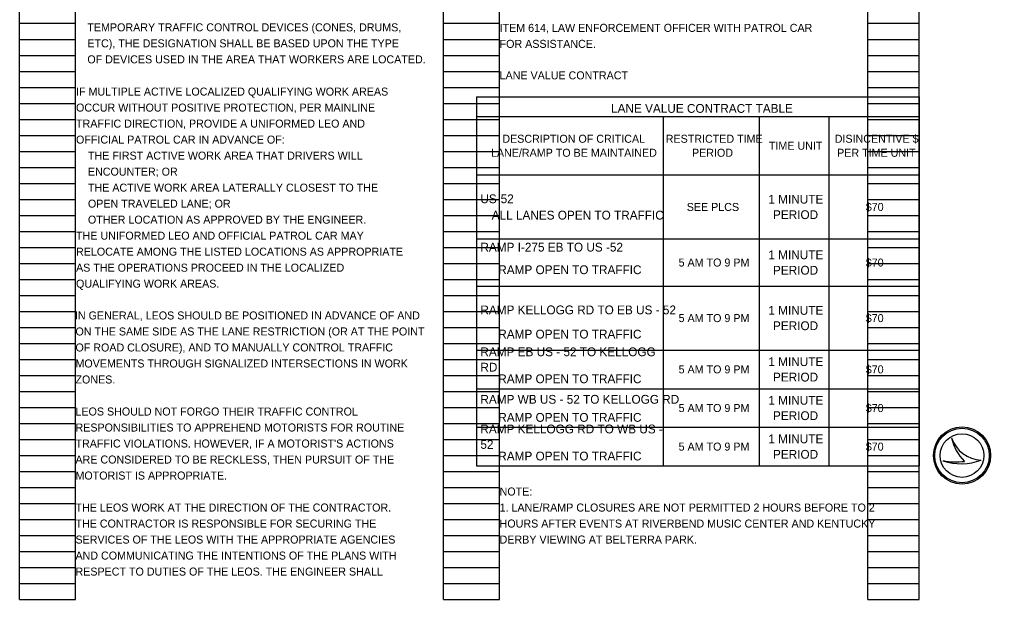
# Model space of a CAD drawing. Extents: x -21.1 to 72.2, y 0 to 46.6.
# Drawn here: x 55.22 to 72.21, y 26.26 to 36.41 of the extents above; entities that cross this region are included whole.
import ezdxf

# ---------------------------------------------------------------- set-up
doc = ezdxf.new("R2010")
doc.units = 0
for name, color, linetype in [('Default', 7, 'Continuous'), ('SH_Data', 7, 'Continuous'), ('SH_Text', 7, 'Continuous')]:
    doc.layers.add(name, color=color, linetype=linetype)

msp = doc.modelspace()

# ---------------------------------------------------------------- linework, layer by layer
at = {"layer": 'Default'}
for p, q in [((63.22, 35.056), (70.962, 35.056)), ((63.22, 35.056), (63.22, 28.6)), ((70.962, 35.056), (70.962, 28.6)), ((63.22, 34.71), (66.482, 34.71)), ((66.482, 34.71), (70.962, 34.71)), ((66.482, 34.71), (66.482, 28.6)), ((68.162, 34.71), (68.162, 28.6)), ((69.38, 34.71), (69.38, 28.6)), ((63.22, 33.689), (70.962, 33.689)), ((63.22, 32.569), (70.962, 32.569)), ((63.22, 31.745), (70.962, 31.745)), ((63.22, 30.625), (70.962, 30.625)), ((63.22, 29.95), (70.962, 29.95)), ((63.22, 29.275), (70.962, 29.275)), ((63.22, 28.6), (70.962, 28.6))]:
    msp.add_line(p, q, dxfattribs=at)
at = {"layer": 'SH_Data'}
for p, q in [((55.222, 26.261), (55.222, 46.421)), ((56.202, 26.261), (56.202, 46.421)), ((62.642, 26.261), (62.642, 46.421)), ((63.622, 26.261), (63.622, 46.421)), ((70.062, 26.261), (70.062, 46.421)), ((70.962, 26.261), (70.962, 46.421)), ((55.222, 36.341), (56.202, 36.341)), ((62.642, 36.341), (63.622, 36.341)), ((70.062, 36.341), (70.962, 36.341)), ((55.222, 36.061), (56.202, 36.061)), ((62.642, 36.061), (63.622, 36.061)), ((70.062, 36.061), (70.962, 36.061)), ((55.222, 35.781), (56.202, 35.781)), ((62.642, 35.781), (63.622, 35.781)), ((70.062, 35.781), (70.962, 35.781)), ((55.222, 35.501), (56.202, 35.501)), ((62.642, 35.501), (63.622, 35.501)), ((70.062, 35.501), (70.962, 35.501)), ((55.222, 35.221), (56.202, 35.221)), ((62.642, 35.221), (63.622, 35.221)), ((70.062, 35.221), (70.962, 35.221)), ((55.222, 34.941), (56.202, 34.941)), ((62.642, 34.941), (63.622, 34.941)), ((70.062, 34.941), (70.962, 34.941)), ((55.222, 34.661), (56.202, 34.661)), ((62.642, 34.661), (63.622, 34.661)), ((70.062, 34.661), (70.962, 34.661)), ((55.222, 34.381), (56.202, 34.381)), ((62.642, 34.381), (63.622, 34.381)), ((70.062, 34.381), (70.962, 34.381)), ((55.222, 34.101), (56.202, 34.101)), ((62.642, 34.101), (63.622, 34.101)), ((70.062, 34.101), (70.962, 34.101)), ((55.222, 33.821), (56.202, 33.821)), ((62.642, 33.821), (63.622, 33.821)), ((70.062, 33.821), (70.962, 33.821)), ((55.222, 33.541), (56.202, 33.541)), ((62.642, 33.541), (63.622, 33.541)), ((70.062, 33.541), (70.962, 33.541)), ((55.222, 33.261), (56.202, 33.261)), ((62.642, 33.261), (63.622, 33.261)), ((70.062, 33.261), (70.962, 33.261)), ((55.222, 32.981), (56.202, 32.981)), ((62.642, 32.981), (63.622, 32.981)), ((70.062, 32.981), (70.962, 32.981)), ((55.222, 32.701), (56.202, 32.701)), ((62.642, 32.701), (63.622, 32.701)), ((70.062, 32.701), (70.962, 32.701)), ((55.222, 32.421), (56.202, 32.421)), ((62.642, 32.421), (63.622, 32.421)), ((70.062, 32.421), (70.962, 32.421)), ((55.222, 32.141), (56.202, 32.141)), ((62.642, 32.141), (63.622, 32.141)), ((70.062, 32.141), (70.962, 32.141)), ((55.222, 31.861), (56.202, 31.861)), ((62.642, 31.861), (63.622, 31.861)), ((70.062, 31.861), (70.962, 31.861)), ((55.222, 31.581), (56.202, 31.581)), ((62.642, 31.581), (63.622, 31.581)), ((70.062, 31.581), (70.962, 31.581)), ((55.222, 31.301), (56.202, 31.301)), ((62.642, 31.301), (63.622, 31.301)), ((70.062, 31.301), (70.962, 31.301)), ((55.222, 31.021), (56.202, 31.021)), ((62.642, 31.021), (63.622, 31.021)), ((70.062, 31.021), (70.962, 31.021)), ((55.222, 30.741), (56.202, 30.741)), ((62.642, 30.741), (63.622, 30.741)), ((70.062, 30.741), (70.962, 30.741)), ((55.222, 30.461), (56.202, 30.461)), ((62.642, 30.461), (63.622, 30.461)), ((70.062, 30.461), (70.962, 30.461)), ((55.222, 30.181), (56.202, 30.181)), ((62.642, 30.181), (63.622, 30.181)), ((70.062, 30.181), (70.962, 30.181)), ((55.222, 29.901), (56.202, 29.901)), ((62.642, 29.901), (63.622, 29.901)), ((70.062, 29.901), (70.962, 29.901)), ((55.222, 29.621), (56.202, 29.621)), ((62.642, 29.621), (63.622, 29.621)), ((70.062, 29.621), (70.962, 29.621)), ((55.222, 29.341), (56.202, 29.341)), ((62.642, 29.341), (63.622, 29.341)), ((70.062, 29.341), (70.962, 29.341)), ((55.222, 29.061), (56.202, 29.061)), ((62.642, 29.061), (63.622, 29.061)), ((70.062, 29.061), (70.962, 29.061)), ((71.529, 29.091), (71.529, 29.091)), ((55.222, 28.781), (56.202, 28.781)), ((62.642, 28.781), (63.622, 28.781)), ((70.062, 28.781), (70.962, 28.781)), ((71.379, 28.691), (71.379, 28.691)), ((72.049, 28.7), (72.049, 28.7)), ((55.222, 28.501), (56.202, 28.501)), ((62.642, 28.501), (63.622, 28.501)), ((70.062, 28.501), (70.962, 28.501)), ((55.222, 28.221), (56.202, 28.221)), ((62.642, 28.221), (63.622, 28.221)), ((70.062, 28.221), (70.962, 28.221)), ((55.222, 27.941), (56.202, 27.941)), ((62.642, 27.941), (63.622, 27.941)), ((70.062, 27.941), (70.962, 27.941)), ((55.222, 27.661), (56.202, 27.661)), ((62.642, 27.661), (63.622, 27.661)), ((70.062, 27.661), (70.962, 27.661)), ((55.222, 27.381), (56.202, 27.381)), ((62.642, 27.381), (63.622, 27.381)), ((70.062, 27.381), (70.962, 27.381)), ((55.222, 27.101), (56.202, 27.101)), ((62.642, 27.101), (63.622, 27.101)), ((70.062, 27.101), (70.962, 27.101)), ((55.222, 26.821), (56.202, 26.821)), ((62.642, 26.821), (63.622, 26.821)), ((70.062, 26.821), (70.962, 26.821)), ((55.222, 26.541), (56.202, 26.541)), ((62.642, 26.541), (63.622, 26.541)), ((70.062, 26.541), (70.962, 26.541)), ((55.222, 26.261), (56.202, 26.261)), ((62.642, 26.261), (63.622, 26.261)), ((70.062, 26.261), (70.962, 26.261))]:
    msp.add_line(p, q, dxfattribs=at)
for radius in [0.5, 0.477, 0.477, 0.382]:
    msp.add_circle((71.712, 28.781), radius, dxfattribs=at)
for centre, radius, start, end in [((72.077, 29.279), 0.58, 198.9257, 198.9319), ((72.308, 29.251), 0.796, 191.6379, 191.6421), ((72.077, 29.279), 0.58, 198.9319, 267.1657), ((72.308, 29.251), 0.796, 191.6421, 226.0947), ((71.701, 29.651), 1.013, 251.4576, 290.0832), ((71.61, 29.936), 1.266, 259.4964, 259.4995), ((71.701, 29.651), 1.013, 251.4527, 251.4576), ((71.61, 29.936), 1.266, 259.4995, 276.6672)]:
    msp.add_arc(centre, radius, start, end, dxfattribs=at)

# ---------------------------------------------------------------- texts
at = {"layer": 'Default'}
for s, height, p in [('LANE VALUE CONTRACT', 0.14, (63.622, 35.361)), ('LANE VALUE CONTRACT TABLE', 0.154, (65.572, 34.776)), ('DESCRIPTION OF CRITICAL ', 0.14, (63.67, 34.252)), ('RESTRICTED TIME ', 0.14, (66.529, 34.252)), ('DISINCENTIVE $ ', 0.14, (69.485, 34.252)), ('LANE/RAMP TO BE MAINTAINED', 0.14, (63.471, 34.007)), ('TIME UNIT', 0.14, (68.333, 34.13)), ('PERIOD', 0.14, (66.988, 34.007)), ('PER TIME UNIT', 0.14, (69.527, 34.007)), ('US-52', 0.154, (63.286, 33.195)), ('1 MINUTE ', 0.154, (68.324, 33.187)), ('SEE PLCS', 0.14, (66.896, 33.059)), ('$70', 0.14, (70.028, 33.059)), ('ALL LANES OPEN TO TRAFFIC', 0.154, (63.484, 32.909)), ('PERIOD', 0.154, (68.405, 32.917)), ('RAMP I-275 EB TO US -52', 0.154, (63.286, 32.349)), ('1 MINUTE ', 0.154, (68.324, 32.215)), ('5 AM TO 9 PM', 0.14, (66.754, 32.087)), ('$70', 0.14, (70.028, 32.087)), ('RAMP OPEN TO TRAFFIC', 0.154, (63.599, 31.954)), ('PERIOD', 0.154, (68.405, 31.945)), ('RAMP KELLOGG RD TO EB US - 52', 0.154, (63.286, 31.251)), ('1 MINUTE ', 0.154, (68.324, 31.243)), ('$70', 0.14, (70.028, 31.115)), ('5 AM TO 9 PM', 0.14, (66.754, 31.115)), ('PERIOD', 0.154, (68.405, 30.974)), ('RAMP OPEN TO TRAFFIC', 0.154, (63.599, 30.828)), ('RAMP EB US - 52 TO KELLOGG ', 0.154, (63.286, 30.518)), ('1 MINUTE ', 0.154, (68.324, 30.346)), ('RD', 0.154, (63.286, 30.249)), ('5 AM TO 9 PM', 0.14, (66.754, 30.218)), ('$70', 0.14, (70.028, 30.218)), ('RAMP OPEN TO TRAFFIC', 0.154, (63.599, 30.046)), ('PERIOD', 0.154, (68.405, 30.076)), ('RAMP WB US - 52 TO KELLOGG RD', 0.154, (63.286, 29.687)), ('1 MINUTE ', 0.154, (68.324, 29.67)), ('5 AM TO 9 PM', 0.14, (66.754, 29.542)), ('$70', 0.14, (70.028, 29.542)), ('RAMP OPEN TO TRAFFIC', 0.154, (63.599, 29.371)), ('PERIOD', 0.154, (68.405, 29.401)), ('RAMP KELLOGG RD TO WB US - ', 0.154, (63.286, 29.168)), ('52', 0.154, (63.286, 28.898)), ('1 MINUTE ', 0.154, (68.324, 28.995)), ('5 AM TO 9 PM', 0.14, (66.754, 28.867)), ('$70', 0.14, (70.028, 28.867)), ('RAMP OPEN TO TRAFFIC', 0.154, (63.599, 28.695)), ('PERIOD', 0.154, (68.405, 28.725)), ('NOTE:', 0.14, (63.622, 28.081)), ('1. LANE/RAMP CLOSURES ARE NOT PERMITTED 2 HOURS BEFORE TO 2', 0.14, (63.622, 27.801)), ('HOURS AFTER EVENTS AT RIVERBEND MUSIC CENTER AND KENTUCKY', 0.14, (63.622, 27.521)), ('DERBY VIEWING AT BELTERRA PARK.', 0.14, (63.622, 27.241))]:
    msp.add_text(s, height=height, dxfattribs=at).set_placement(p)
at = {"layer": 'SH_Text'}
for s, p in [('    TEMPORARY TRAFFIC CONTROL DEVICES (CONES, DRUMS,', (56.202, 36.201)), ('ITEM 614, LAW ENFORCEMENT OFFICER WITH PATROL CAR', (63.622, 36.192)), ('    ETC), THE DESIGNATION SHALL BE BASED UPON THE TYPE', (56.202, 35.921)), ('FOR ASSISTANCE.', (63.622, 35.912)), ('    OF DEVICES USED IN THE AREA THAT WORKERS ARE LOCATED.', (56.202, 35.641)), ('    IF MULTIPLE ACTIVE LOCALIZED QUALIFYING WORK AREAS', (56.004, 35.077)), ('    OCCUR WITHOUT POSITIVE PROTECTION, PER MAINLINE', (56.004, 34.797)), ('    TRAFFIC DIRECTION, PROVIDE A UNIFORMED LEO AND', (56.004, 34.517)), ('    OFFICIAL PATROL CAR IN ADVANCE OF:', (56.004, 34.237)), ('        THE FIRST ACTIVE WORK AREA THAT DRIVERS WILL', (56.004, 33.957)), ('        ENCOUNTER; OR', (56.004, 33.677)), ('        THE ACTIVE WORK AREA LATERALLY CLOSEST TO THE', (56.004, 33.397)), ('        OPEN TRAVELED LANE; OR', (56.004, 33.117)), ('        OTHER LOCATION AS APPROVED BY THE ENGINEER.', (56.004, 32.837)), ('    THE UNIFORMED LEO AND OFFICIAL PATROL CAR MAY', (56.004, 32.557)), ('    RELOCATE AMONG THE LISTED LOCATIONS AS APPROPRIATE', (56.004, 32.277)), ('    AS THE OPERATIONS PROCEED IN THE LOCALIZED', (56.004, 31.997)), ('    QUALIFYING WORK AREAS.', (56.004, 31.717)), ('IN GENERAL, LEOS SHOULD BE POSITIONED IN ADVANCE OF AND', (56.193, 31.161)), ('ON THE SAME SIDE AS THE LANE RESTRICTION (OR AT THE POINT', (56.202, 30.881)), ('OF ROAD CLOSURE), AND TO MANUALLY CONTROL TRAFFIC', (56.202, 30.601)), ('MOVEMENTS THROUGH SIGNALIZED INTERSECTIONS IN WORK', (56.202, 30.321)), ('ZONES.', (56.202, 30.041)), ('LEOS SHOULD NOT FORGO THEIR TRAFFIC CONTROL', (56.202, 29.481)), ('RESPONSIBILITIES TO APPREHEND MOTORISTS FOR ROUTINE', (56.202, 29.201)), ("TRAFFIC VIOLATIONS. HOWEVER, IF A MOTORIST'S ACTIONS", (56.202, 28.921)), ('ARE CONSIDERED TO BE RECKLESS, THEN PURSUIT OF THE', (56.202, 28.641)), ('MOTORIST IS APPROPRIATE.', (56.202, 28.361)), ('THE LEOS WORK AT THE DIRECTION OF THE CONTRACTOR.', (56.202, 27.801)), ('THE CONTRACTOR IS RESPONSIBLE FOR SECURING THE', (56.202, 27.521)), ('SERVICES OF THE LEOS WITH THE APPROPRIATE AGENCIES', (56.202, 27.241)), ('AND COMMUNICATING THE INTENTIONS OF THE PLANS WITH', (56.202, 26.961)), ('RESPECT TO DUTIES OF THE LEOS. THE ENGINEER SHALL', (56.202, 26.681))]:
    msp.add_text(s, height=0.14, dxfattribs=at).set_placement(p)

doc.saveas('drawing.dxf')
